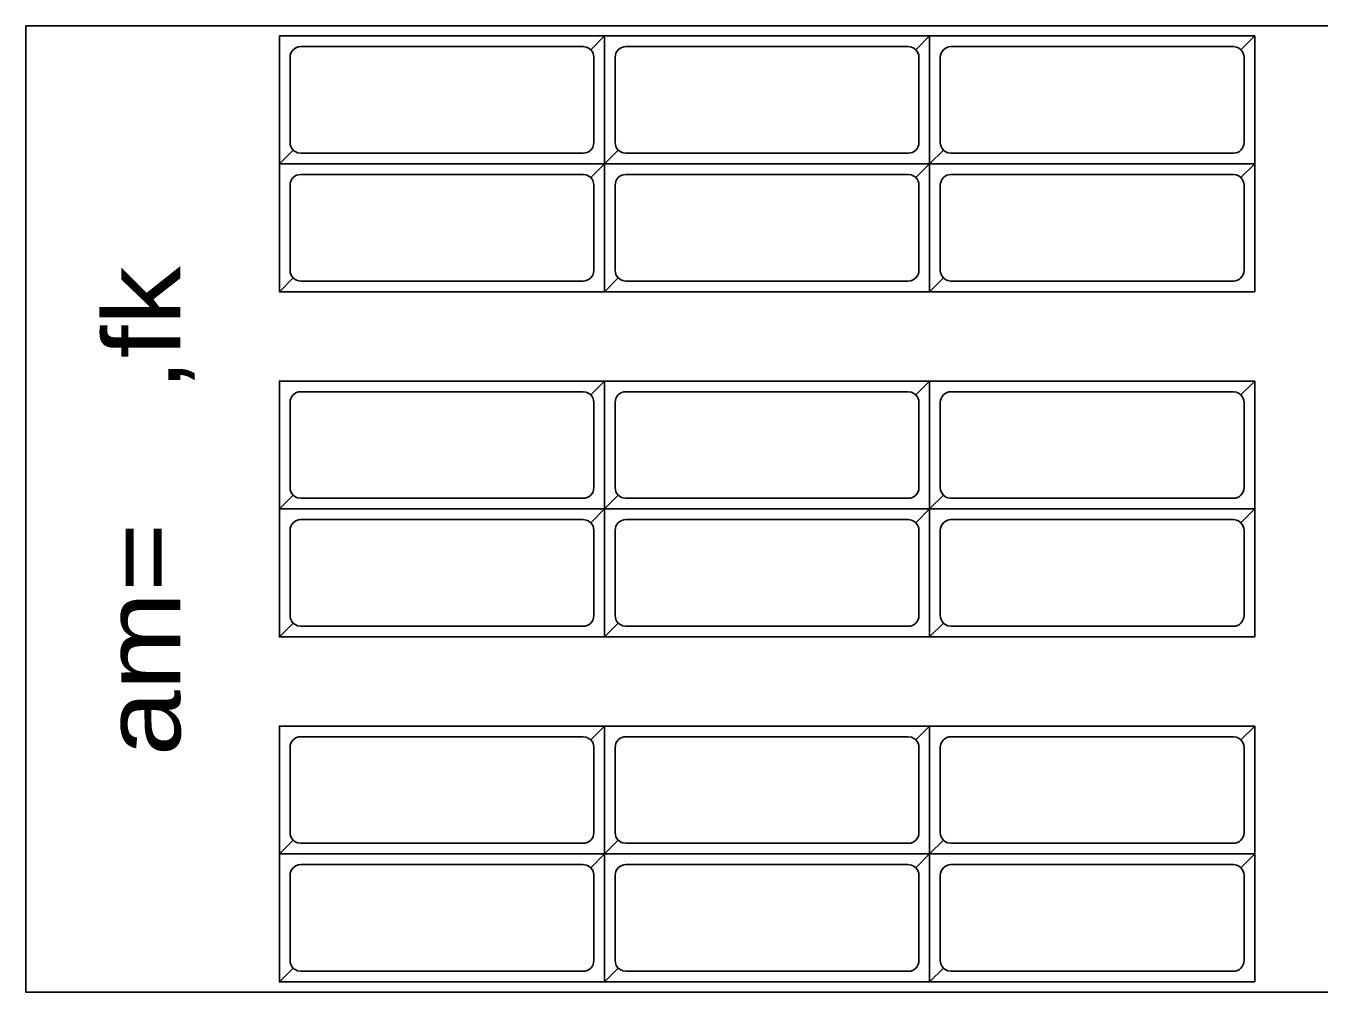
# Model space of a CAD drawing. Extents: x 16898 to 16911.6, y 15837.8 to 15842.
# Drawn here: x 16897.996 to 16900.726, y 15837.832 to 15839.872 of the extents above; entities that cross this region are included whole.
import ezdxf
from ezdxf.enums import TextEntityAlignment as Align

# ---------------------------------------------------------------- set-up
doc = ezdxf.new("R2010")
doc.units = 0
doc.header["$LTSCALE"] = 0.018
doc.layers.add('1', color=7, linetype='Continuous', lineweight=25)
doc.layers.add('2', color=7, linetype='Continuous', lineweight=13)

msp = doc.modelspace()

# ---------------------------------------------------------------- linework, layer by layer
at = {"layer": '1'}
for points in [[(16897.9955, 15837.8322), (16897.9955, 15839.8723), (16911.4764, 15839.8723), (16911.5674, 15839.785), (16911.5674, 15837.9198), (16911.4764, 15837.8322)], [(16898.5308, 15839.581), (16899.2172, 15839.581), (16899.2172, 15839.851), (16898.5308, 15839.851)], [(16898.5308, 15839.581), (16899.2172, 15839.581), (16899.2172, 15839.851), (16899.1881, 15839.8219), (16899.1909, 15839.8185), (16899.193, 15839.8146), (16899.1942, 15839.8104), (16899.1947, 15839.806), (16899.1947, 15839.626), (16899.1942, 15839.6216), (16899.193, 15839.6174), (16899.1909, 15839.6135), (16899.1881, 15839.6101), (16899.1881, 15839.6101), (16899.1847, 15839.6073), (16899.1808, 15839.6052), (16899.1766, 15839.6039), (16899.1722, 15839.6035), (16898.5758, 15839.6035), (16898.5692, 15839.6045), (16898.5652, 15839.6062), (16898.5615, 15839.6086), (16898.5599, 15839.6101)], [(16899.2172, 15839.851), (16898.5308, 15839.851), (16898.5308, 15839.581), (16898.5599, 15839.6101), (16898.5571, 15839.6135), (16898.555, 15839.6174), (16898.5537, 15839.6216), (16898.5533, 15839.626), (16898.5533, 15839.806), (16898.5537, 15839.8104), (16898.555, 15839.8146), (16898.5571, 15839.8185), (16898.5599, 15839.8219), (16898.5599, 15839.8219), (16898.5633, 15839.8247), (16898.5672, 15839.8268), (16898.5714, 15839.828), (16898.5758, 15839.8285), (16899.1722, 15839.8285), (16899.1788, 15839.8275), (16899.1828, 15839.8258), (16899.1865, 15839.8234), (16899.1881, 15839.8219)], [(16899.2172, 15839.581), (16899.9036, 15839.581), (16899.9036, 15839.851), (16899.2172, 15839.851)], [(16899.2172, 15839.581), (16899.9036, 15839.581), (16899.9036, 15839.851), (16899.8745, 15839.8219), (16899.8773, 15839.8185), (16899.8794, 15839.8146), (16899.8806, 15839.8104), (16899.8811, 15839.806), (16899.8811, 15839.626), (16899.8806, 15839.6216), (16899.8794, 15839.6174), (16899.8773, 15839.6135), (16899.8745, 15839.6101), (16899.8745, 15839.6101), (16899.8711, 15839.6073), (16899.8672, 15839.6052), (16899.863, 15839.6039), (16899.8586, 15839.6035), (16899.2622, 15839.6035), (16899.2556, 15839.6045), (16899.2516, 15839.6062), (16899.2479, 15839.6086), (16899.2463, 15839.6101)], [(16899.9036, 15839.851), (16899.2172, 15839.851), (16899.2172, 15839.581), (16899.2463, 15839.6101), (16899.2435, 15839.6135), (16899.2414, 15839.6174), (16899.2401, 15839.6216), (16899.2397, 15839.626), (16899.2397, 15839.806), (16899.2401, 15839.8104), (16899.2414, 15839.8146), (16899.2435, 15839.8185), (16899.2463, 15839.8219), (16899.2463, 15839.8219), (16899.2497, 15839.8247), (16899.2536, 15839.8268), (16899.2578, 15839.828), (16899.2622, 15839.8285), (16899.8586, 15839.8285), (16899.8652, 15839.8275), (16899.8692, 15839.8258), (16899.8729, 15839.8234), (16899.8745, 15839.8219)], [(16899.9036, 15839.581), (16900.59, 15839.581), (16900.59, 15839.851), (16899.9036, 15839.851)], [(16899.9036, 15839.581), (16900.59, 15839.581), (16900.59, 15839.851), (16900.5609, 15839.8219), (16900.5637, 15839.8185), (16900.5658, 15839.8146), (16900.567, 15839.8104), (16900.5675, 15839.806), (16900.5675, 15839.626), (16900.567, 15839.6216), (16900.5658, 15839.6174), (16900.5637, 15839.6135), (16900.5609, 15839.6101), (16900.5609, 15839.6101), (16900.5575, 15839.6073), (16900.5536, 15839.6052), (16900.5494, 15839.6039), (16900.545, 15839.6035), (16899.9486, 15839.6035), (16899.942, 15839.6045), (16899.938, 15839.6062), (16899.9343, 15839.6086), (16899.9327, 15839.6101)], [(16900.59, 15839.851), (16899.9036, 15839.851), (16899.9036, 15839.581), (16899.9327, 15839.6101), (16899.9299, 15839.6135), (16899.9278, 15839.6174), (16899.9265, 15839.6216), (16899.9261, 15839.626), (16899.9261, 15839.806), (16899.9265, 15839.8104), (16899.9278, 15839.8146), (16899.9299, 15839.8185), (16899.9327, 15839.8219), (16899.9327, 15839.8219), (16899.9361, 15839.8247), (16899.94, 15839.8268), (16899.9442, 15839.828), (16899.9486, 15839.8285), (16900.545, 15839.8285), (16900.5516, 15839.8275), (16900.5556, 15839.8258), (16900.5593, 15839.8234), (16900.5609, 15839.8219)], [(16898.5308, 15839.311), (16899.2172, 15839.311), (16899.2172, 15839.581), (16898.5308, 15839.581)], [(16898.5308, 15839.311), (16899.2172, 15839.311), (16899.2172, 15839.581), (16899.1881, 15839.5519), (16899.1909, 15839.5485), (16899.193, 15839.5446), (16899.1942, 15839.5404), (16899.1947, 15839.536), (16899.1947, 15839.356), (16899.1942, 15839.3516), (16899.193, 15839.3474), (16899.1909, 15839.3435), (16899.1881, 15839.3401), (16899.1881, 15839.3401), (16899.1847, 15839.3373), (16899.1808, 15839.3352), (16899.1766, 15839.3339), (16899.1722, 15839.3335), (16898.5758, 15839.3335), (16898.5692, 15839.3345), (16898.5652, 15839.3362), (16898.5615, 15839.3386), (16898.5599, 15839.3401)], [(16899.2172, 15839.581), (16898.5308, 15839.581), (16898.5308, 15839.311), (16898.5599, 15839.3401), (16898.5571, 15839.3435), (16898.555, 15839.3474), (16898.5537, 15839.3516), (16898.5533, 15839.356), (16898.5533, 15839.536), (16898.5537, 15839.5404), (16898.555, 15839.5446), (16898.5571, 15839.5485), (16898.5599, 15839.5519), (16898.5599, 15839.5519), (16898.5633, 15839.5547), (16898.5672, 15839.5568), (16898.5714, 15839.558), (16898.5758, 15839.5585), (16899.1722, 15839.5585), (16899.1788, 15839.5575), (16899.1828, 15839.5558), (16899.1865, 15839.5534), (16899.1881, 15839.5519)], [(16899.2172, 15839.311), (16899.9036, 15839.311), (16899.9036, 15839.581), (16899.2172, 15839.581)], [(16899.2172, 15839.311), (16899.9036, 15839.311), (16899.9036, 15839.581), (16899.8745, 15839.5519), (16899.8773, 15839.5485), (16899.8794, 15839.5446), (16899.8806, 15839.5404), (16899.8811, 15839.536), (16899.8811, 15839.356), (16899.8806, 15839.3516), (16899.8794, 15839.3474), (16899.8773, 15839.3435), (16899.8745, 15839.3401), (16899.8745, 15839.3401), (16899.8711, 15839.3373), (16899.8672, 15839.3352), (16899.863, 15839.3339), (16899.8586, 15839.3335), (16899.2622, 15839.3335), (16899.2556, 15839.3345), (16899.2516, 15839.3362), (16899.2479, 15839.3386), (16899.2463, 15839.3401)], [(16899.9036, 15839.581), (16899.2172, 15839.581), (16899.2172, 15839.311), (16899.2463, 15839.3401), (16899.2435, 15839.3435), (16899.2414, 15839.3474), (16899.2401, 15839.3516), (16899.2397, 15839.356), (16899.2397, 15839.536), (16899.2401, 15839.5404), (16899.2414, 15839.5446), (16899.2435, 15839.5485), (16899.2463, 15839.5519), (16899.2463, 15839.5519), (16899.2497, 15839.5547), (16899.2536, 15839.5568), (16899.2578, 15839.558), (16899.2622, 15839.5585), (16899.8586, 15839.5585), (16899.8652, 15839.5575), (16899.8692, 15839.5558), (16899.8729, 15839.5534), (16899.8745, 15839.5519)], [(16899.9036, 15839.311), (16900.59, 15839.311), (16900.59, 15839.581), (16899.9036, 15839.581)], [(16899.9036, 15839.311), (16900.59, 15839.311), (16900.59, 15839.581), (16900.5609, 15839.5519), (16900.5637, 15839.5485), (16900.5658, 15839.5446), (16900.567, 15839.5404), (16900.5675, 15839.536), (16900.5675, 15839.356), (16900.567, 15839.3516), (16900.5658, 15839.3474), (16900.5637, 15839.3435), (16900.5609, 15839.3401), (16900.5609, 15839.3401), (16900.5575, 15839.3373), (16900.5536, 15839.3352), (16900.5494, 15839.3339), (16900.545, 15839.3335), (16899.9486, 15839.3335), (16899.942, 15839.3345), (16899.938, 15839.3362), (16899.9343, 15839.3386), (16899.9327, 15839.3401)], [(16900.59, 15839.581), (16899.9036, 15839.581), (16899.9036, 15839.311), (16899.9327, 15839.3401), (16899.9299, 15839.3435), (16899.9278, 15839.3474), (16899.9265, 15839.3516), (16899.9261, 15839.356), (16899.9261, 15839.536), (16899.9265, 15839.5404), (16899.9278, 15839.5446), (16899.9299, 15839.5485), (16899.9327, 15839.5519), (16899.9327, 15839.5519), (16899.9361, 15839.5547), (16899.94, 15839.5568), (16899.9442, 15839.558), (16899.9486, 15839.5585), (16900.545, 15839.5585), (16900.5516, 15839.5575), (16900.5556, 15839.5558), (16900.5593, 15839.5534), (16900.5609, 15839.5519)], [(16898.5308, 15838.8523), (16899.2172, 15838.8523), (16899.2172, 15839.1223), (16898.5308, 15839.1223)], [(16898.5308, 15838.8523), (16899.2172, 15838.8523), (16899.2172, 15839.1223), (16899.1881, 15839.0932), (16899.1909, 15839.0898), (16899.193, 15839.0859), (16899.1942, 15839.0817), (16899.1947, 15839.0773), (16899.1947, 15838.8973), (16899.1942, 15838.8929), (16899.193, 15838.8887), (16899.1909, 15838.8848), (16899.1881, 15838.8814), (16899.1881, 15838.8814), (16899.1847, 15838.8786), (16899.1808, 15838.8765), (16899.1766, 15838.8752), (16899.1722, 15838.8748), (16898.5758, 15838.8748), (16898.5692, 15838.8758), (16898.5652, 15838.8775), (16898.5615, 15838.8799), (16898.5599, 15838.8814)], [(16899.2172, 15839.1223), (16898.5308, 15839.1223), (16898.5308, 15838.8523), (16898.5599, 15838.8814), (16898.5571, 15838.8848), (16898.555, 15838.8887), (16898.5537, 15838.8929), (16898.5533, 15838.8973), (16898.5533, 15839.0773), (16898.5537, 15839.0817), (16898.555, 15839.0859), (16898.5571, 15839.0898), (16898.5599, 15839.0932), (16898.5599, 15839.0932), (16898.5633, 15839.096), (16898.5672, 15839.0981), (16898.5714, 15839.0993), (16898.5758, 15839.0998), (16899.1722, 15839.0998), (16899.1788, 15839.0988), (16899.1828, 15839.0971), (16899.1865, 15839.0947), (16899.1881, 15839.0932)], [(16899.2172, 15838.8523), (16899.9036, 15838.8523), (16899.9036, 15839.1223), (16899.2172, 15839.1223)], [(16899.2172, 15838.8523), (16899.9036, 15838.8523), (16899.9036, 15839.1223), (16899.8745, 15839.0932), (16899.8773, 15839.0898), (16899.8794, 15839.0859), (16899.8806, 15839.0817), (16899.8811, 15839.0773), (16899.8811, 15838.8973), (16899.8806, 15838.8929), (16899.8794, 15838.8887), (16899.8773, 15838.8848), (16899.8745, 15838.8814), (16899.8745, 15838.8814), (16899.8711, 15838.8786), (16899.8672, 15838.8765), (16899.863, 15838.8752), (16899.8586, 15838.8748), (16899.2622, 15838.8748), (16899.2556, 15838.8758), (16899.2516, 15838.8775), (16899.2479, 15838.8799), (16899.2463, 15838.8814)], [(16899.9036, 15839.1223), (16899.2172, 15839.1223), (16899.2172, 15838.8523), (16899.2463, 15838.8814), (16899.2435, 15838.8848), (16899.2414, 15838.8887), (16899.2401, 15838.8929), (16899.2397, 15838.8973), (16899.2397, 15839.0773), (16899.2401, 15839.0817), (16899.2414, 15839.0859), (16899.2435, 15839.0898), (16899.2463, 15839.0932), (16899.2463, 15839.0932), (16899.2497, 15839.096), (16899.2536, 15839.0981), (16899.2578, 15839.0993), (16899.2622, 15839.0998), (16899.8586, 15839.0998), (16899.8652, 15839.0988), (16899.8692, 15839.0971), (16899.8729, 15839.0947), (16899.8745, 15839.0932)], [(16899.9036, 15838.8523), (16900.59, 15838.8523), (16900.59, 15839.1223), (16899.9036, 15839.1223)], [(16899.9036, 15838.8523), (16900.59, 15838.8523), (16900.59, 15839.1223), (16900.5609, 15839.0932), (16900.5637, 15839.0898), (16900.5658, 15839.0859), (16900.567, 15839.0817), (16900.5675, 15839.0773), (16900.5675, 15838.8973), (16900.567, 15838.8929), (16900.5658, 15838.8887), (16900.5637, 15838.8848), (16900.5609, 15838.8814), (16900.5609, 15838.8814), (16900.5575, 15838.8786), (16900.5536, 15838.8765), (16900.5494, 15838.8752), (16900.545, 15838.8748), (16899.9486, 15838.8748), (16899.942, 15838.8758), (16899.938, 15838.8775), (16899.9343, 15838.8799), (16899.9327, 15838.8814)], [(16900.59, 15839.1223), (16899.9036, 15839.1223), (16899.9036, 15838.8523), (16899.9327, 15838.8814), (16899.9299, 15838.8848), (16899.9278, 15838.8887), (16899.9265, 15838.8929), (16899.9261, 15838.8973), (16899.9261, 15839.0773), (16899.9265, 15839.0817), (16899.9278, 15839.0859), (16899.9299, 15839.0898), (16899.9327, 15839.0932), (16899.9327, 15839.0932), (16899.9361, 15839.096), (16899.94, 15839.0981), (16899.9442, 15839.0993), (16899.9486, 15839.0998), (16900.545, 15839.0998), (16900.5516, 15839.0988), (16900.5556, 15839.0971), (16900.5593, 15839.0947), (16900.5609, 15839.0932)], [(16898.5308, 15838.5823), (16899.2172, 15838.5823), (16899.2172, 15838.8523), (16898.5308, 15838.8523)], [(16898.5308, 15838.5823), (16899.2172, 15838.5823), (16899.2172, 15838.8523), (16899.1881, 15838.8232), (16899.1909, 15838.8198), (16899.193, 15838.8159), (16899.1942, 15838.8117), (16899.1947, 15838.8073), (16899.1947, 15838.6273), (16899.1942, 15838.6229), (16899.193, 15838.6187), (16899.1909, 15838.6148), (16899.1881, 15838.6114), (16899.1881, 15838.6114), (16899.1847, 15838.6086), (16899.1808, 15838.6065), (16899.1766, 15838.6052), (16899.1722, 15838.6048), (16898.5758, 15838.6048), (16898.5692, 15838.6058), (16898.5652, 15838.6075), (16898.5615, 15838.6099), (16898.5599, 15838.6114)], [(16899.2172, 15838.8523), (16898.5308, 15838.8523), (16898.5308, 15838.5823), (16898.5599, 15838.6114), (16898.5571, 15838.6148), (16898.555, 15838.6187), (16898.5537, 15838.6229), (16898.5533, 15838.6273), (16898.5533, 15838.8073), (16898.5537, 15838.8117), (16898.555, 15838.8159), (16898.5571, 15838.8198), (16898.5599, 15838.8232), (16898.5599, 15838.8232), (16898.5633, 15838.826), (16898.5672, 15838.8281), (16898.5714, 15838.8293), (16898.5758, 15838.8298), (16899.1722, 15838.8298), (16899.1788, 15838.8288), (16899.1828, 15838.8271), (16899.1865, 15838.8247), (16899.1881, 15838.8232)], [(16899.2172, 15838.5823), (16899.9036, 15838.5823), (16899.9036, 15838.8523), (16899.2172, 15838.8523)], [(16899.2172, 15838.5823), (16899.9036, 15838.5823), (16899.9036, 15838.8523), (16899.8745, 15838.8232), (16899.8773, 15838.8198), (16899.8794, 15838.8159), (16899.8806, 15838.8117), (16899.8811, 15838.8073), (16899.8811, 15838.6273), (16899.8806, 15838.6229), (16899.8794, 15838.6187), (16899.8773, 15838.6148), (16899.8745, 15838.6114), (16899.8745, 15838.6114), (16899.8711, 15838.6086), (16899.8672, 15838.6065), (16899.863, 15838.6052), (16899.8586, 15838.6048), (16899.2622, 15838.6048), (16899.2556, 15838.6058), (16899.2516, 15838.6075), (16899.2479, 15838.6099), (16899.2463, 15838.6114)], [(16899.9036, 15838.8523), (16899.2172, 15838.8523), (16899.2172, 15838.5823), (16899.2463, 15838.6114), (16899.2435, 15838.6148), (16899.2414, 15838.6187), (16899.2401, 15838.6229), (16899.2397, 15838.6273), (16899.2397, 15838.8073), (16899.2401, 15838.8117), (16899.2414, 15838.8159), (16899.2435, 15838.8198), (16899.2463, 15838.8232), (16899.2463, 15838.8232), (16899.2497, 15838.826), (16899.2536, 15838.8281), (16899.2578, 15838.8293), (16899.2622, 15838.8298), (16899.8586, 15838.8298), (16899.8652, 15838.8288), (16899.8692, 15838.8271), (16899.8729, 15838.8247), (16899.8745, 15838.8232)], [(16899.9036, 15838.5823), (16900.59, 15838.5823), (16900.59, 15838.8523), (16899.9036, 15838.8523)], [(16899.9036, 15838.5823), (16900.59, 15838.5823), (16900.59, 15838.8523), (16900.5609, 15838.8232), (16900.5637, 15838.8198), (16900.5658, 15838.8159), (16900.567, 15838.8117), (16900.5675, 15838.8073), (16900.5675, 15838.6273), (16900.567, 15838.6229), (16900.5658, 15838.6187), (16900.5637, 15838.6148), (16900.5609, 15838.6114), (16900.5609, 15838.6114), (16900.5575, 15838.6086), (16900.5536, 15838.6065), (16900.5494, 15838.6052), (16900.545, 15838.6048), (16899.9486, 15838.6048), (16899.942, 15838.6058), (16899.938, 15838.6075), (16899.9343, 15838.6099), (16899.9327, 15838.6114)], [(16900.59, 15838.8523), (16899.9036, 15838.8523), (16899.9036, 15838.5823), (16899.9327, 15838.6114), (16899.9299, 15838.6148), (16899.9278, 15838.6187), (16899.9265, 15838.6229), (16899.9261, 15838.6273), (16899.9261, 15838.8073), (16899.9265, 15838.8117), (16899.9278, 15838.8159), (16899.9299, 15838.8198), (16899.9327, 15838.8232), (16899.9327, 15838.8232), (16899.9361, 15838.826), (16899.94, 15838.8281), (16899.9442, 15838.8293), (16899.9486, 15838.8298), (16900.545, 15838.8298), (16900.5516, 15838.8288), (16900.5556, 15838.8271), (16900.5593, 15838.8247), (16900.5609, 15838.8232)], [(16898.5308, 15838.1239), (16899.2172, 15838.1239), (16899.2172, 15838.3939), (16898.5308, 15838.3939)], [(16898.5308, 15838.1239), (16899.2172, 15838.1239), (16899.2172, 15838.3939), (16899.1881, 15838.3648), (16899.1909, 15838.3614), (16899.193, 15838.3575), (16899.1942, 15838.3533), (16899.1947, 15838.3489), (16899.1947, 15838.1689), (16899.1942, 15838.1645), (16899.193, 15838.1603), (16899.1909, 15838.1564), (16899.1881, 15838.153), (16899.1881, 15838.153), (16899.1847, 15838.1502), (16899.1808, 15838.1481), (16899.1766, 15838.1468), (16899.1722, 15838.1464), (16898.5758, 15838.1464), (16898.5692, 15838.1474), (16898.5652, 15838.1491), (16898.5615, 15838.1515), (16898.5599, 15838.153)], [(16899.2172, 15838.3939), (16898.5308, 15838.3939), (16898.5308, 15838.1239), (16898.5599, 15838.153), (16898.5571, 15838.1564), (16898.555, 15838.1603), (16898.5537, 15838.1645), (16898.5533, 15838.1689), (16898.5533, 15838.3489), (16898.5537, 15838.3533), (16898.555, 15838.3575), (16898.5571, 15838.3614), (16898.5599, 15838.3648), (16898.5599, 15838.3648), (16898.5633, 15838.3676), (16898.5672, 15838.3697), (16898.5714, 15838.3709), (16898.5758, 15838.3714), (16899.1722, 15838.3714), (16899.1788, 15838.3704), (16899.1828, 15838.3687), (16899.1865, 15838.3663), (16899.1881, 15838.3648)], [(16899.2172, 15838.1239), (16899.9036, 15838.1239), (16899.9036, 15838.3939), (16899.2172, 15838.3939)], [(16899.2172, 15838.1239), (16899.9036, 15838.1239), (16899.9036, 15838.3939), (16899.8745, 15838.3648), (16899.8773, 15838.3614), (16899.8794, 15838.3575), (16899.8806, 15838.3533), (16899.8811, 15838.3489), (16899.8811, 15838.1689), (16899.8806, 15838.1645), (16899.8794, 15838.1603), (16899.8773, 15838.1564), (16899.8745, 15838.153), (16899.8745, 15838.153), (16899.8711, 15838.1502), (16899.8672, 15838.1481), (16899.863, 15838.1468), (16899.8586, 15838.1464), (16899.2622, 15838.1464), (16899.2556, 15838.1474), (16899.2516, 15838.1491), (16899.2479, 15838.1515), (16899.2463, 15838.153)], [(16899.9036, 15838.3939), (16899.2172, 15838.3939), (16899.2172, 15838.1239), (16899.2463, 15838.153), (16899.2435, 15838.1564), (16899.2414, 15838.1603), (16899.2401, 15838.1645), (16899.2397, 15838.1689), (16899.2397, 15838.3489), (16899.2401, 15838.3533), (16899.2414, 15838.3575), (16899.2435, 15838.3614), (16899.2463, 15838.3648), (16899.2463, 15838.3648), (16899.2497, 15838.3676), (16899.2536, 15838.3697), (16899.2578, 15838.3709), (16899.2622, 15838.3714), (16899.8586, 15838.3714), (16899.8652, 15838.3704), (16899.8692, 15838.3687), (16899.8729, 15838.3663), (16899.8745, 15838.3648)], [(16899.9036, 15838.1239), (16900.59, 15838.1239), (16900.59, 15838.3939), (16899.9036, 15838.3939)], [(16899.9036, 15838.1239), (16900.59, 15838.1239), (16900.59, 15838.3939), (16900.5609, 15838.3648), (16900.5637, 15838.3614), (16900.5658, 15838.3575), (16900.567, 15838.3533), (16900.5675, 15838.3489), (16900.5675, 15838.1689), (16900.567, 15838.1645), (16900.5658, 15838.1603), (16900.5637, 15838.1564), (16900.5609, 15838.153), (16900.5609, 15838.153), (16900.5575, 15838.1502), (16900.5536, 15838.1481), (16900.5494, 15838.1468), (16900.545, 15838.1464), (16899.9486, 15838.1464), (16899.942, 15838.1474), (16899.938, 15838.1491), (16899.9343, 15838.1515), (16899.9327, 15838.153)], [(16900.59, 15838.3939), (16899.9036, 15838.3939), (16899.9036, 15838.1239), (16899.9327, 15838.153), (16899.9299, 15838.1564), (16899.9278, 15838.1603), (16899.9265, 15838.1645), (16899.9261, 15838.1689), (16899.9261, 15838.3489), (16899.9265, 15838.3533), (16899.9278, 15838.3575), (16899.9299, 15838.3614), (16899.9327, 15838.3648), (16899.9327, 15838.3648), (16899.9361, 15838.3676), (16899.94, 15838.3697), (16899.9442, 15838.3709), (16899.9486, 15838.3714), (16900.545, 15838.3714), (16900.5516, 15838.3704), (16900.5556, 15838.3687), (16900.5593, 15838.3663), (16900.5609, 15838.3648)], [(16898.5308, 15837.8539), (16899.2172, 15837.8539), (16899.2172, 15838.1239), (16898.5308, 15838.1239)], [(16898.5308, 15837.8539), (16899.2172, 15837.8539), (16899.2172, 15838.1239), (16899.1881, 15838.0948), (16899.1909, 15838.0914), (16899.193, 15838.0875), (16899.1942, 15838.0833), (16899.1947, 15838.0789), (16899.1947, 15837.8989), (16899.1942, 15837.8945), (16899.193, 15837.8903), (16899.1909, 15837.8864), (16899.1881, 15837.883), (16899.1881, 15837.883), (16899.1847, 15837.8802), (16899.1808, 15837.8781), (16899.1766, 15837.8768), (16899.1722, 15837.8764), (16898.5758, 15837.8764), (16898.5692, 15837.8774), (16898.5652, 15837.8791), (16898.5615, 15837.8815), (16898.5599, 15837.883)], [(16899.2172, 15838.1239), (16898.5308, 15838.1239), (16898.5308, 15837.8539), (16898.5599, 15837.883), (16898.5571, 15837.8864), (16898.555, 15837.8903), (16898.5537, 15837.8945), (16898.5533, 15837.8989), (16898.5533, 15838.0789), (16898.5537, 15838.0833), (16898.555, 15838.0875), (16898.5571, 15838.0914), (16898.5599, 15838.0948), (16898.5599, 15838.0948), (16898.5633, 15838.0976), (16898.5672, 15838.0997), (16898.5714, 15838.1009), (16898.5758, 15838.1014), (16899.1722, 15838.1014), (16899.1788, 15838.1004), (16899.1828, 15838.0987), (16899.1865, 15838.0963), (16899.1881, 15838.0948)], [(16899.2172, 15837.8539), (16899.9036, 15837.8539), (16899.9036, 15838.1239), (16899.2172, 15838.1239)], [(16899.2172, 15837.8539), (16899.9036, 15837.8539), (16899.9036, 15838.1239), (16899.8745, 15838.0948), (16899.8773, 15838.0914), (16899.8794, 15838.0875), (16899.8806, 15838.0833), (16899.8811, 15838.0789), (16899.8811, 15837.8989), (16899.8806, 15837.8945), (16899.8794, 15837.8903), (16899.8773, 15837.8864), (16899.8745, 15837.883), (16899.8745, 15837.883), (16899.8711, 15837.8802), (16899.8672, 15837.8781), (16899.863, 15837.8768), (16899.8586, 15837.8764), (16899.2622, 15837.8764), (16899.2556, 15837.8774), (16899.2516, 15837.8791), (16899.2479, 15837.8815), (16899.2463, 15837.883)], [(16899.9036, 15838.1239), (16899.2172, 15838.1239), (16899.2172, 15837.8539), (16899.2463, 15837.883), (16899.2435, 15837.8864), (16899.2414, 15837.8903), (16899.2401, 15837.8945), (16899.2397, 15837.8989), (16899.2397, 15838.0789), (16899.2401, 15838.0833), (16899.2414, 15838.0875), (16899.2435, 15838.0914), (16899.2463, 15838.0948), (16899.2463, 15838.0948), (16899.2497, 15838.0976), (16899.2536, 15838.0997), (16899.2578, 15838.1009), (16899.2622, 15838.1014), (16899.8586, 15838.1014), (16899.8652, 15838.1004), (16899.8692, 15838.0987), (16899.8729, 15838.0963), (16899.8745, 15838.0948)], [(16899.9036, 15837.8539), (16900.59, 15837.8539), (16900.59, 15838.1239), (16899.9036, 15838.1239)], [(16899.9036, 15837.8539), (16900.59, 15837.8539), (16900.59, 15838.1239), (16900.5609, 15838.0948), (16900.5637, 15838.0914), (16900.5658, 15838.0875), (16900.567, 15838.0833), (16900.5675, 15838.0789), (16900.5675, 15837.8989), (16900.567, 15837.8945), (16900.5658, 15837.8903), (16900.5637, 15837.8864), (16900.5609, 15837.883), (16900.5609, 15837.883), (16900.5575, 15837.8802), (16900.5536, 15837.8781), (16900.5494, 15837.8768), (16900.545, 15837.8764), (16899.9486, 15837.8764), (16899.942, 15837.8774), (16899.938, 15837.8791), (16899.9343, 15837.8815), (16899.9327, 15837.883)], [(16900.59, 15838.1239), (16899.9036, 15838.1239), (16899.9036, 15837.8539), (16899.9327, 15837.883), (16899.9299, 15837.8864), (16899.9278, 15837.8903), (16899.9265, 15837.8945), (16899.9261, 15837.8989), (16899.9261, 15838.0789), (16899.9265, 15838.0833), (16899.9278, 15838.0875), (16899.9299, 15838.0914), (16899.9327, 15838.0948), (16899.9327, 15838.0948), (16899.9361, 15838.0976), (16899.94, 15838.0997), (16899.9442, 15838.1009), (16899.9486, 15838.1014), (16900.545, 15838.1014), (16900.5516, 15838.1004), (16900.5556, 15838.0987), (16900.5593, 15838.0963), (16900.5609, 15838.0948)]]:
    msp.add_lwpolyline(points, close=True, dxfattribs=at)
at = {"layer": '2'}
msp.add_lwpolyline([(16897.9955, 15837.8324), (16897.9955, 15839.8723), (16911.4764, 15839.8723), (16911.5674, 15839.785), (16911.5674, 15837.9197), (16911.4764, 15837.8324)], close=True, dxfattribs=at)

# ---------------------------------------------------------------- texts
at = {"layer": '1', "width": 1.15}
msp.add_text('am=    ,fk', height=0.1625, rotation=90, dxfattribs=at).set_placement((16898.3218, 15838.8476), align=Align.CENTER)

doc.saveas('drawing.dxf')
